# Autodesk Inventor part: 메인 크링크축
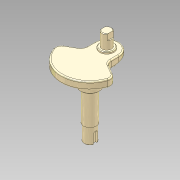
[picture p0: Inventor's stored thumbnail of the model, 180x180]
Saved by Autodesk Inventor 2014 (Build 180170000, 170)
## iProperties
Manager: KYOUNG IL JANG
Company: 한국ATC센터
Created: 2012-10
Part Number: 메인 크링크축
Document SubType Name: Modeling
Density: 1 g/cm^3
Checked By: KYOUNG IL JANG
Vendor: CBT Solutions
Designer: KYOUNG IL JANG
Material: Generic
Appearance: _시험_금속-티타늄(광택)
크링크폭: 19.000 mm
크랭크길이: 18.000 mm
크랭키위치: 65.000 mm
무게추: 90.000 mm
크랭크각도높이: 21.000 mm
크링크각도: -15.00 deg
Author: KYOUNG IL JANG
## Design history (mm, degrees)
sketch "스케치1"
  geometry: L1 (-19, 109.368)-(-19, 91.368); L2 (-19, 91.368)-(-44.545, 76.619); L3 (19, 109.368)-(19, 91.368); L4 (19, 91.368)-(44.545, 76.619); C1 r 32.5 at (0, 83) reference; C2 r 10 at (0, 83); C3 r 17.5 at (0, 83); A1 r 45 centre (0, 83) between (-44.545, 76.619) and (44.545, 76.619); A2 r 32.5 centre (0, 83) between (-19, 109.368) and (19, 109.368); A3 r 19 centre (0, 109.368) between (19, 109.368) and (-19, 109.368); 1 further point
  constraints: 8 end point, 6 point on circle, 5 centre point, 4 coincident, 2 equal length, 2 vertical alignment, 1 horizontal alignment, 1 parallel, 1 tangent, 1 vertical, 3 other
  dimensions: "d0" = 20 diameter of C2; "d1" = 35 diameter of C3; "d4" = 120 deg angle of L3 L4
extrude "돌출1" new body sketch "스케치1" distance "d7" = 12; taper "d8" = 0 deg
extrude "돌출2" join sketch "스케치1" distance "d9" = 5; taper "d10" = 0 deg
extrude "돌출3" join sketch "스케치1" distance "d11" = 100; taper "d12" = 0 deg
sketch "스케치2"
  geometry: C1 r 7.5 at (0, 109.368); C2 r 11 at (0, 109.368); A1 r 19 centre (0, 109.368) between (19, 109.368) and (-19, 109.368) reference; 1 further point
  constraints: 2 centre point, 2 coincident
  dimensions: "d13" = 15 diameter of C1; "d14" = 22 diameter of C2
extrude "돌출4" join sketch "스케치2" distance "d15" = 3; taper "d16" = 0 deg
extrude "돌출5" join sketch "스케치2" distance "d17" = 25; taper "d18" = 0 deg
node "작업 평면1"
sketch "스케치3"
  geometry: L1 (-5.75, 4.815)-(-5.75, -4.815); L2 (5.75, 4.815)-(5.75, -4.815); A1 r 7.5 centre (0, 0) between (-5.75, 4.815) and (-5.75, -4.815) reference; 1 further point
  constraints: 4 end point, 4 point on circle, 2 parallel, 1 vertical
  dimensions: "d20" = 11.5 distance between parallel lines of L2 L1
extrude "돌출6" cut sketch "스케치3" stored distance "d21" = 10; taper "d22" = 0 deg
node "작업 평면2"
  node "작업축1"
sketch "스케치5"
  geometry: L1 (0, 0)-(38, 0); L2 (38, 0)-(38, 50); L3 (38, 50)-(0, 50); L4 (0, 50)-(0, 0); L5 (38, 5.185)-(38, -12.202) reference; 2 further points
  constraints: 8 end point, 1 coincident, 1 collinear, 1 horizontal, 1 perpendicular
  dimensions: "d27" = 50 distance between parallel lines of L3 L1
extrude "돌출7" cut sketch "스케치5" stored distance "d28" = 10; taper "d29" = 0 deg
fillet "모깎기1" dims "d23" = 10, "d24" = 2
sketch "스케치6"
  geometry: C1 r 17.5 at (0, 0) reference; C2 r 15 at (0, 0); 1 further point
  constraints: 1 centre point, 1 coincident
  dimensions: "d30" = 30 diameter of C2
extrude "돌출8" join sketch "스케치6" distance "d31" = 21; taper "d32" = 0 deg
sketch "스케치7"
  geometry: C1 r 10 at (0, 0) reference; C2 r 9 at (0, 0); 1 further point
  constraints: 1 centre point, 1 coincident
  dimensions: "d33" = 1 radial gap between concentric circles of C1 C2
extrude "돌출9" cut sketch "스케치7" distance "d34" = 25; taper "d35" = 0 deg
node "작업 평면3"
sketch "스케치8"
  geometry: L1 (-9, 0)-(9, 0) reference; L2 (-3, 0)-(-3, 15); L3 (3, 15)-(3, 0); A1 r 3 centre (0, 15) between (3, 15) and (-3, 15); 2 further points
  constraints: 4 end point, 2 perpendicular, 2 point on circle, 2 point on line, 2 tangent, 1 centre point, 1 midpoint, 1 vertical alignment
  dimensions: "d36" = 6 distance between parallel lines of L3 L2; "d37" = 18 dimension on A1 L1
extrude "돌출10" cut sketch "스케치8" distance "d38" = 3.5; taper "d39" = 0 deg
chamfer "모따기1" distance "d40" = 1; stored, may be unused: second distance "d41" = 2, angle "d42" = 45 deg
node "솔리드1"
sketch "스케치4"
  geometry: L1 (-19, 91.368)-(-19, 109.368) reference; L2 (19, 109.368)-(19, 91.368) reference; C1 r 17.5 at (0, 83) reference; 3 further points
  constraints: 2 point on line, 1 horizontal alignment, 1 other
node "참조1"
node "투영된 루프1"
other parameters: "d19" = 13
